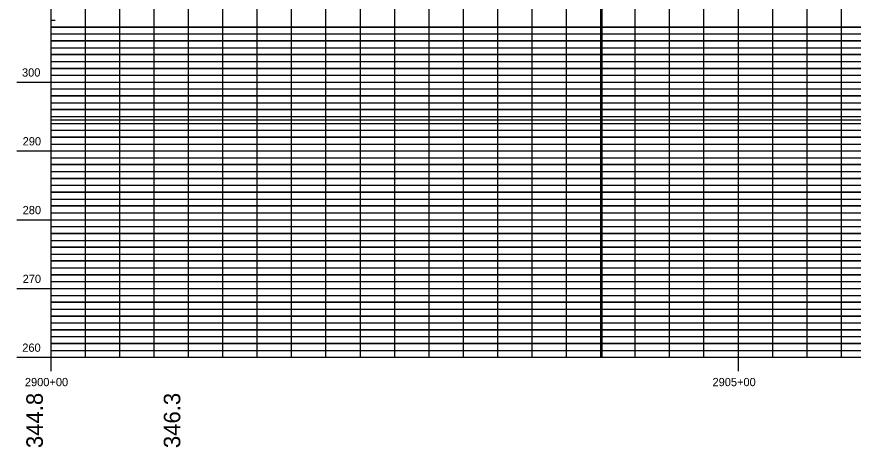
# Model space of a CAD drawing. Extents: x 1195880 to 1289360, y 2059330 to 2086925.
# Drawn here: x 1200369 to 1200977, y 2063535 to 2063848 of the extents above; entities that cross this region are included whole.
import ezdxf

# ---------------------------------------------------------------- set-up
doc = ezdxf.new("R2010")
doc.units = 0
for name, color, linetype in [('41', 7, 'Continuous'), ('51', 7, 'Continuous'), ('Default', 7, 'Continuous'), ('Grid', 7, 'Continuous'), ('Grid Lables', 7, 'Continuous')]:
    doc.layers.add(name, color=color, linetype=linetype)

msp = doc.modelspace()

# ---------------------------------------------------------------- linework, layer by layer
at = {"layer": 'Default'}
for p, q in [((1200794.61, 2063600.38), (1200794.61, 2064081.02)), ((1200393.62, 2063600.38), (1200794.61, 2063600.38)), ((1200393.62, 2063600.38), (1201319.42, 2063600.38))]:
    msp.add_line(p, q, dxfattribs=at)
at = {"layer": 'Grid'}
for p, q in [((1200393.62, 2063600.38), (1200393.62, 2064350.38)), ((1200418.62, 2063600.38), (1200418.62, 2064350.38)), ((1200443.62, 2063600.38), (1200443.62, 2064350.38)), ((1200468.62, 2063600.38), (1200468.62, 2064350.38)), ((1200493.62, 2063600.38), (1200493.62, 2064350.38)), ((1200518.62, 2063600.38), (1200518.62, 2064350.38)), ((1200543.62, 2063600.38), (1200543.62, 2064350.38)), ((1200568.62, 2063600.38), (1200568.62, 2064350.38)), ((1200593.62, 2063600.38), (1200593.62, 2064350.38)), ((1200618.62, 2063600.38), (1200618.62, 2064350.38)), ((1200643.62, 2063600.38), (1200643.62, 2064350.38)), ((1200668.62, 2063600.38), (1200668.62, 2064350.38)), ((1200693.62, 2063600.38), (1200693.62, 2064350.38)), ((1200718.62, 2063600.38), (1200718.62, 2064350.38)), ((1200743.62, 2063600.38), (1200743.62, 2064350.38)), ((1200768.62, 2063600.38), (1200768.62, 2064350.38)), ((1200793.62, 2063600.38), (1200793.62, 2064350.38)), ((1200818.62, 2063600.38), (1200818.62, 2064350.38)), ((1200843.62, 2063600.38), (1200843.62, 2064350.38)), ((1200868.62, 2063600.38), (1200868.62, 2064350.38)), ((1200893.62, 2063600.38), (1200893.62, 2064350.38)), ((1200918.62, 2063600.38), (1200918.62, 2064350.38)), ((1200943.62, 2063600.38), (1200943.62, 2064350.38)), ((1200968.62, 2063600.38), (1200968.62, 2064350.38)), ((1200393.62, 2063845.38), (1200396.62, 2063845.38)), ((1200393.62, 2063840.38), (1200396.62, 2063840.38)), ((1200393.62, 2063840.38), (1201893.62, 2063840.38)), ((1201893.62, 2063840.38), (1200393.62, 2063840.38)), ((1200393.62, 2063835.38), (1200396.62, 2063835.38)), ((1200393.62, 2063835.38), (1201893.62, 2063835.38)), ((1200393.62, 2063830.38), (1200396.62, 2063830.38)), ((1200393.62, 2063830.38), (1201893.62, 2063830.38)), ((1201893.62, 2063830.38), (1200393.62, 2063830.38)), ((1200393.62, 2063825.38), (1200396.62, 2063825.38)), ((1200393.62, 2063825.38), (1201893.62, 2063825.38)), ((1200393.62, 2063820.38), (1200396.62, 2063820.38)), ((1200393.62, 2063820.38), (1201893.62, 2063820.38)), ((1201893.62, 2063820.38), (1200393.62, 2063820.38)), ((1200393.62, 2063815.38), (1200396.62, 2063815.38)), ((1200393.62, 2063815.38), (1201893.62, 2063815.38)), ((1200393.62, 2063810.38), (1200396.62, 2063810.38)), ((1200393.62, 2063810.38), (1201893.62, 2063810.38)), ((1201893.62, 2063810.38), (1200393.62, 2063810.38)), ((1200393.62, 2063805.38), (1200396.62, 2063805.38)), ((1200393.62, 2063805.38), (1201893.62, 2063805.38)), ((1200368.62, 2063800.38), (1200393.62, 2063800.38)), ((1200393.62, 2063800.38), (1201893.62, 2063800.38)), ((1200393.62, 2063795.38), (1200396.62, 2063795.38)), ((1200393.62, 2063795.38), (1201893.62, 2063795.38)), ((1200393.62, 2063790.38), (1200396.62, 2063790.38)), ((1200393.62, 2063790.38), (1201893.62, 2063790.38)), ((1201893.62, 2063790.38), (1200393.62, 2063790.38)), ((1200393.62, 2063785.38), (1200396.62, 2063785.38)), ((1200393.62, 2063785.38), (1201893.62, 2063785.38)), ((1200393.62, 2063780.38), (1200396.62, 2063780.38)), ((1200393.62, 2063780.38), (1201893.62, 2063780.38)), ((1201893.62, 2063780.38), (1200393.62, 2063780.38)), ((1200393.62, 2063775.38), (1200396.62, 2063775.38)), ((1200393.62, 2063775.38), (1201893.62, 2063775.38)), ((1201893.62, 2063772.78), (1200393.62, 2063772.78)), ((1200393.62, 2063770.38), (1200396.62, 2063770.38)), ((1200393.62, 2063770.38), (1201893.62, 2063770.38)), ((1200393.62, 2063765.38), (1200396.62, 2063765.38)), ((1200393.62, 2063765.38), (1201893.62, 2063765.38)), ((1200393.62, 2063760.38), (1200396.62, 2063760.38)), ((1200393.62, 2063760.38), (1201893.62, 2063760.38)), ((1201893.62, 2063760.38), (1200393.62, 2063760.38)), ((1200393.62, 2063755.38), (1200396.62, 2063755.38)), ((1200393.62, 2063755.38), (1201893.62, 2063755.38)), ((1200368.62, 2063750.38), (1200393.62, 2063750.38)), ((1200393.62, 2063750.38), (1201893.62, 2063750.38)), ((1200393.62, 2063745.38), (1200396.62, 2063745.38)), ((1200393.62, 2063745.38), (1201893.62, 2063745.38)), ((1200393.62, 2063740.38), (1200396.62, 2063740.38)), ((1200393.62, 2063740.38), (1201893.62, 2063740.38)), ((1201893.62, 2063740.38), (1200393.62, 2063740.38)), ((1200393.62, 2063735.38), (1200396.62, 2063735.38)), ((1200393.62, 2063735.38), (1201893.62, 2063735.38)), ((1200393.62, 2063730.38), (1200396.62, 2063730.38)), ((1200393.62, 2063730.38), (1201893.62, 2063730.38)), ((1201893.62, 2063730.38), (1200393.62, 2063730.38)), ((1200393.62, 2063725.38), (1200396.62, 2063725.38)), ((1200393.62, 2063725.38), (1201893.62, 2063725.38)), ((1200393.62, 2063720.38), (1200396.62, 2063720.38)), ((1200393.62, 2063720.38), (1201893.62, 2063720.38)), ((1201893.62, 2063720.38), (1200393.62, 2063720.38)), ((1200393.62, 2063715.38), (1200396.62, 2063715.38)), ((1200393.62, 2063715.38), (1201893.62, 2063715.38)), ((1200393.62, 2063710.38), (1200396.62, 2063710.38)), ((1200393.62, 2063710.38), (1201893.62, 2063710.38)), ((1201893.62, 2063710.38), (1200393.62, 2063710.38)), ((1200393.62, 2063705.38), (1200396.62, 2063705.38)), ((1200393.62, 2063705.38), (1201893.62, 2063705.38)), ((1200368.62, 2063700.38), (1200393.62, 2063700.38)), ((1200393.62, 2063700.38), (1201893.62, 2063700.38)), ((1200393.62, 2063695.38), (1200396.62, 2063695.38)), ((1200393.62, 2063695.38), (1201893.62, 2063695.38)), ((1200393.62, 2063690.38), (1200396.62, 2063690.38)), ((1200393.62, 2063690.38), (1201893.62, 2063690.38)), ((1201893.62, 2063690.38), (1200393.62, 2063690.38)), ((1200393.62, 2063685.38), (1200396.62, 2063685.38)), ((1200393.62, 2063685.38), (1201893.62, 2063685.38)), ((1200393.62, 2063680.38), (1200396.62, 2063680.38)), ((1200393.62, 2063680.38), (1201893.62, 2063680.38)), ((1201893.62, 2063680.38), (1200393.62, 2063680.38)), ((1200393.62, 2063675.38), (1200396.62, 2063675.38)), ((1200393.62, 2063675.38), (1201893.62, 2063675.38)), ((1200393.62, 2063670.38), (1200396.62, 2063670.38)), ((1200393.62, 2063670.38), (1201893.62, 2063670.38)), ((1201893.62, 2063670.38), (1200393.62, 2063670.38)), ((1200393.62, 2063665.38), (1200396.62, 2063665.38)), ((1200393.62, 2063665.38), (1201893.62, 2063665.38)), ((1200393.62, 2063660.38), (1200396.62, 2063660.38)), ((1200393.62, 2063660.38), (1201893.62, 2063660.38)), ((1201893.62, 2063660.38), (1200393.62, 2063660.38)), ((1200393.62, 2063655.38), (1200396.62, 2063655.38)), ((1200393.62, 2063655.38), (1201893.62, 2063655.38)), ((1200368.62, 2063650.38), (1200393.62, 2063650.38)), ((1200393.62, 2063650.38), (1201893.62, 2063650.38)), ((1200393.62, 2063645.38), (1200396.62, 2063645.38)), ((1200393.62, 2063645.38), (1201893.62, 2063645.38)), ((1200393.62, 2063640.38), (1200396.62, 2063640.38)), ((1200393.62, 2063640.38), (1201893.62, 2063640.38)), ((1201893.62, 2063640.38), (1200393.62, 2063640.38)), ((1200393.62, 2063635.38), (1200396.62, 2063635.38)), ((1200393.62, 2063635.38), (1201893.62, 2063635.38)), ((1200393.62, 2063630.38), (1200396.62, 2063630.38)), ((1200393.62, 2063630.38), (1201893.62, 2063630.38)), ((1201893.62, 2063630.38), (1200393.62, 2063630.38)), ((1200393.62, 2063625.38), (1200396.62, 2063625.38)), ((1200393.62, 2063625.38), (1201893.62, 2063625.38)), ((1200393.62, 2063620.38), (1200396.62, 2063620.38)), ((1200393.62, 2063620.38), (1201893.62, 2063620.38)), ((1201893.62, 2063620.38), (1200393.62, 2063620.38)), ((1200393.62, 2063615.38), (1200396.62, 2063615.38)), ((1200393.62, 2063615.38), (1201893.62, 2063615.38)), ((1200393.62, 2063610.38), (1200396.62, 2063610.38)), ((1200393.62, 2063610.38), (1201893.62, 2063610.38)), ((1201893.62, 2063610.38), (1200393.62, 2063610.38)), ((1200393.62, 2063605.38), (1200396.62, 2063605.38)), ((1200393.62, 2063605.38), (1201893.62, 2063605.38)), ((1200418.62, 2063600.38), (1200418.62, 2063603.38)), ((1200443.62, 2063600.38), (1200443.62, 2063603.38)), ((1200468.62, 2063600.38), (1200468.62, 2063603.38)), ((1200493.62, 2063600.38), (1200493.62, 2063603.38)), ((1200518.62, 2063600.38), (1200518.62, 2063603.38)), ((1200543.62, 2063600.38), (1200543.62, 2063603.38)), ((1200568.62, 2063600.38), (1200568.62, 2063603.38)), ((1200593.62, 2063600.38), (1200593.62, 2063603.38)), ((1200618.62, 2063600.38), (1200618.62, 2063603.38)), ((1200643.62, 2063600.38), (1200643.62, 2063603.38)), ((1200668.62, 2063600.38), (1200668.62, 2063603.38)), ((1200693.62, 2063600.38), (1200693.62, 2063603.38)), ((1200718.62, 2063600.38), (1200718.62, 2063603.38)), ((1200743.62, 2063600.38), (1200743.62, 2063603.38)), ((1200768.62, 2063600.38), (1200768.62, 2063603.38)), ((1200793.62, 2063600.38), (1200793.62, 2063603.38)), ((1200818.62, 2063600.38), (1200818.62, 2063603.38)), ((1200843.62, 2063600.38), (1200843.62, 2063603.38)), ((1200868.62, 2063600.38), (1200868.62, 2063603.38)), ((1200918.62, 2063600.38), (1200918.62, 2063603.38)), ((1200943.62, 2063600.38), (1200943.62, 2063603.38)), ((1200968.62, 2063600.38), (1200968.62, 2063603.38)), ((1200368.62, 2063600.38), (1200393.62, 2063600.38)), ((1200393.62, 2063600.38), (1201893.62, 2063600.38)), ((1200393.62, 2063590.38), (1200393.62, 2063600.38)), ((1200893.62, 2063590.38), (1200893.62, 2063600.38))]:
    msp.add_line(p, q, dxfattribs=at)

# ---------------------------------------------------------------- texts
at = {"layer": '41'}
for s, p in [('344.8', (1200387.62, 2063534.38)), ('346.3', (1200487.62, 2063534.38))]:
    msp.add_text(s, height=12, rotation=90, dxfattribs=at).set_placement(p)
at = {"layer": '51'}
msp.add_text('-', height=0.0001, dxfattribs=at).set_placement((1200393.62, 2063600.38))
at = {"layer": 'Grid Lables'}
for s, p in [('300', (1200372.46, 2063804.38)), ('290', (1200372.93, 2063754.38)), ('280', (1200372.93, 2063704.38)), ('270', (1200372.93, 2063654.38)), ('260', (1200372.65, 2063604.38)), ('2900+00', (1200374.56, 2063579.38)), ('2905+00', (1200874.8, 2063579.38))]:
    msp.add_text(s, height=6, dxfattribs=at).set_placement(p)

doc.saveas('drawing.dxf')
